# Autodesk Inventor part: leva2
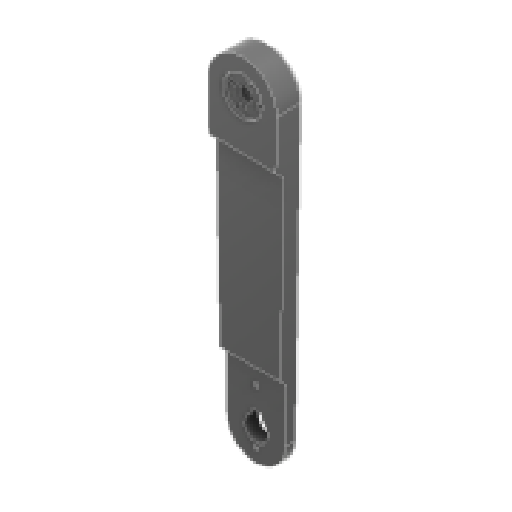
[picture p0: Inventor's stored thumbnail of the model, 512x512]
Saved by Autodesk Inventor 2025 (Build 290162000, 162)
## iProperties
Created: 2025-05
Part Number: leva2
Material: Plastica ABS
Document SubType Name: Modeling
Designer: R5800u
Density: 1.06 g/cm^3
Appearance: Liscia - Nero
Author: R5800u
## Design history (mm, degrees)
sketch "Schizzo1"
  geometry: L1 (-17.498, 149.708)-(-14.998, -0.25); L2 (17.498, 149.708)-(14.998, -0.25); L3 (0, 0)-(0, 150); A1 r 15 centre (0, 0) between (-14.998, -0.25) and (14.998, -0.25); A2 r 17.5 centre (0, 150) between (-17.498, 149.708) and (17.498, 149.708); 1 further point
  constraints: 6 end point, 4 point on circle, 4 tangent, 2 centre point, 2 coincident, 1 vertical
  dimensions: "d0" = 30 diameter of A1; "d1" = 35 diameter of A2; "d28" = 150 distance of L3.start L3.end
extrude "Estrusione1" new body sketch "Schizzo1" distance "d3" = 10; taper "d4" = 0 deg
sketch "Schizzo2"
  geometry: L1 (-17.498, 149.708)-(-14.998, -0.25) reference; L2 (14.998, -0.25)-(17.498, 149.708) reference; L3 (-17.498, 149.708)-(-14.998, -0.25) reference; L4 (-17.09, 125.281)-(17.081, 124.712); A1 r 15 centre (0, 0) between (-14.998, -0.25) and (14.998, -0.25) reference; A2 r 17.5 centre (0, 150) between (17.498, 149.708) and (-17.498, 149.708) reference; 2 further points
  constraints: 2 end point, 2 point on line, 1 perpendicular
  dimensions: "d5" = 25 distance from line of L4 A2.centre
extrude "Estrusione2" join sketch "Schizzo2" distance "d6" = 4; taper "d7" = 0 deg
sketch "Schizzo3"
  geometry: C1 r 10 at (0, 150); A1 r 17.5 centre (0, 150) between (17.498, 149.708) and (-17.498, 149.708) reference; 1 further point
  constraints: 1 centre point, 1 coincident
  dimensions: "d8" = 20 diameter of C1
extrude "Estrusione3" cut sketch "Schizzo3" distance "d9" = 2; taper "d10" = 0 deg
sketch "Schizzo4"
  geometry: C1 r 10 at (0, 0) reference; 2 further points
  constraints: 1 coincident
hole "Foro1" sketch "Schizzo4" at (0, 0) diameter "d11" = 3.2; stored, may be unused: countersink angle "d15" = 90 deg, drill point angle "d17" = 118 deg; dims "d12" = 6, "d13" = 7, "d14" = 3, "d16" = 8
chamfer "Smusso1" distance "d18" = 4; stored, may be unused: second distance "d19" = 2, angle "d20" = 45 deg
sketch "Schizzo5"
  geometry: 1 further point
hole "Foro2" sketch "Schizzo5" at (0, 0) diameter "d21" = 12; stored, may be unused: countersink angle "d25" = 90 deg, drill point angle "d27" = 118 deg; dims "d22" = 6, "d23" = 7, "d24" = 2, "d26" = 8
sketch "Schizzo6"
  geometry: L1 (-17.024, 121.28)-(17.014, 120.712) reference; L2 (-17.024, 121.28)-(-14.998, -0.25) reference; L3 (14.998, -0.25)-(17.014, 120.712) reference; L4 (0, 150)-(0, 0); L5 (15.502, 30)-(-15.502, 30); C1 r 6 at (0, 0) reference; C2 r 1.6 at (0, 150) reference; A1 r 15 centre (0, 0) between (-14.998, -0.25) and (14.998, -0.25) reference; 1 further point
  constraints: 4 end point, 2 point on line, 1 horizontal
  dimensions: "d34" = 30 distance from line of L5 point (0, 0)
extrude "Estrusione4" cut sketch "Schizzo6" distance "d29" = 3; taper "d30" = 0 deg
chamfer "Smusso2" distance "d31" = 3; stored, may be unused: second distance "d32" = 2, angle "d33" = 45 deg
sketch "Schizzo7"
  geometry: C1 r 2 at (0, 0) reference; A1 r 2.5 centre (0, 5.9) between (2.326, 4.984) and (-2.326, 4.984) reference; A2 r 5.5 centre (0, 0) between (-2.326, 4.984) and (2.326, 4.984) reference; A3 r 2.8 centre (0, 5.9) between (2.694, 5.136) and (-2.694, 5.136); A4 r 5.8 centre (0, 0) between (-2.694, 5.136) and (2.694, 5.136); 1 further point
  constraints: 4 point on circle, 2 centre point, 1 other
  dimensions: "d35" = 0.3 radial gap between concentric circles of A1 A3
extrude "Estrusione5" cut sketch "Schizzo7" distance "d36" = 3; taper "d37" = 0 deg
sketch "Schizzo8"
  geometry: A1 r 1 centre (0, -8.05) between (0.5, -8.916) and (-0.5, -8.916) reference; A2 r 1 centre (0, 19.35) between (-0.5, 20.216) and (0.5, 20.216) reference; 1 further point
  node "Riferimento2"
  node "Riferimento3"
sketch "Schizzo9"
  geometry: C1 r 1.25 at (-2.037, 156.697) reference; C2 r 1.25 at (6.697, 152.037) reference; C3 r 1.25 at (2.037, 143.303) reference; C4 r 1.25 at (-6.697, 147.963) reference; 1 further point
hole "Foro3" sketch "Schizzo9" at (-6.697, 147.963), (2.037, 143.303), (6.697, 152.037), (-2.037, 156.697) diameter "d38" = 3.2; stored, may be unused: countersink angle "d42" = 90 deg, drill point angle "d44" = 118 deg; dims "d39" = 6, "d40" = 11, "d41" = 2.6, "d43" = 8
sketch "Schizzo10"
  geometry: C1 r 1.6 at (0, 150) reference; 2 further points
  constraints: 1 coincident
hole "Foro4" sketch "Schizzo10" at (0, 150) diameter "d45" = 3.2; stored, may be unused: countersink angle "d49" = 90 deg, drill point angle "d51" = 118 deg; dims "d46" = 6, "d47" = 6, "d48" = 2.6, "d50" = 8
hole "Foro5" sketch "Schizzo8" diameter "d52" = 2.5; stored, may be unused: countersink angle "d56" = 90 deg, drill point angle "d58" = 118 deg; dims "d53" = 6, "d54" = 6, "d55" = 2.6, "d57" = 8
chamfer "Smusso3" distance "d59" = 2; stored, may be unused: second distance "d60" = 2, angle "d61" = 45 deg
node "Solido1"
node "Linea chiusa proiettata1"
node "Linea chiusa proiettata2"
node "Riferimento1"
node "Riferimento4"
node "Riferimento5"
node "Riferimento6"
node "Riferimento7"
